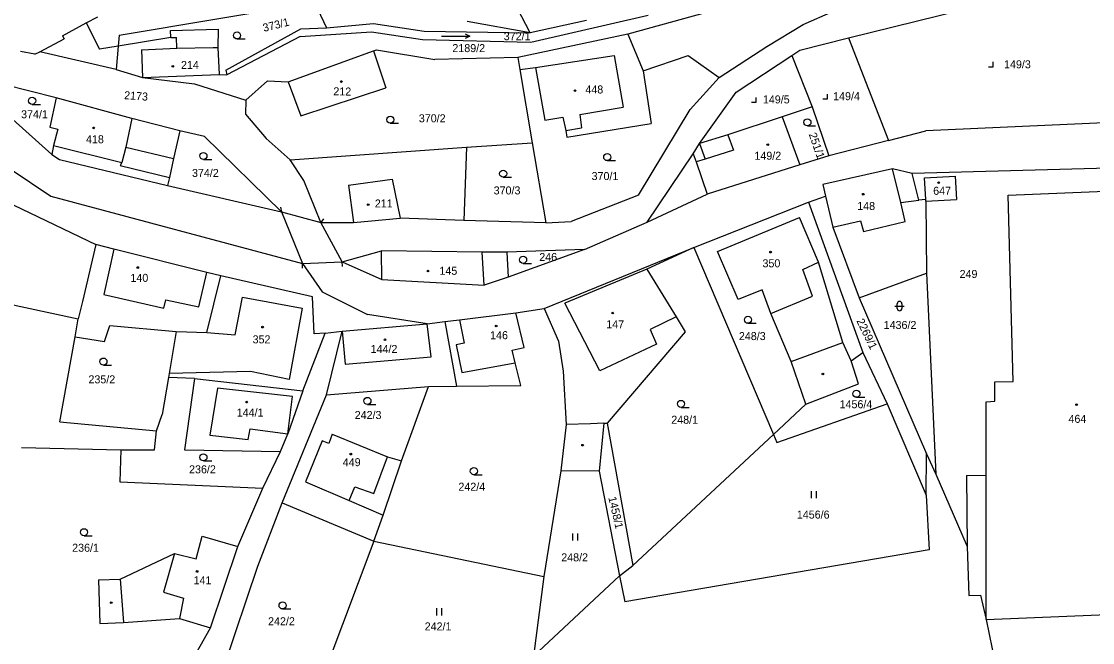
# Model space of a CAD drawing. Extents: x -717507 to -715515, y -957700 to -954941.
# Drawn here: x -717201.2 to -716973.6, y -957575.6 to -957443.7 of the extents above; entities that cross this region are included whole.
import ezdxf

# ---------------------------------------------------------------- set-up
doc = ezdxf.new("R2010")
doc.units = 0
for name, color, linetype in [('Hranice parcel', 7, 'Continuous'), ('Parcelní čísla', 7, 'Continuous'), ('Vnitřní kresba', 7, 'Continuous'), ('Značky budov', 7, 'Continuous'), ('Značky kultur', 7, 'Continuous')]:
    doc.layers.add(name, color=color, linetype=linetype)

msp = doc.modelspace()

# ---------------------------------------------------------------- linework, layer by layer
at = {"layer": 'Hranice parcel'}
for points in [[(-717028.63, -957434.3), (-717072.34, -957446.43)], [(-717025.46, -957447.15), (-716968.22, -957433.04)], [(-717093.05, -957446.09), (-717097.51, -957437.46)], [(-717180.41, -957446.62), (-717138.91, -957439.67)], [(-717138.91, -957439.67), (-717136.37, -957445.05)], [(-717035.09, -957444.35), (-717028.62, -957441.53)], [(-717187.43, -957444), (-717184.92, -957442.75)], [(-717187.43, -957444), (-717184.56, -957449.6)], [(-717093.05, -957446.09), (-717106.48, -957443.69)], [(-717081.13, -957443.5), (-717093.05, -957446.09)], [(-717092.95, -957448.11), (-717068.02, -957442.34)], [(-717169.47, -957445.61), (-717159.36, -957445.32)], [(-717169.45, -957447.09), (-717169.47, -957445.61)], [(-717159.36, -957445.32), (-717159.42, -957449.22)], [(-717157.74, -957454.03), (-717141.81, -957445.24)], [(-717141.93, -957446.89), (-717126.79, -957445.88)], [(-717141.81, -957445.24), (-717136.37, -957445.05)], [(-717136.37, -957445.05), (-717126.34, -957444.17)], [(-717126.79, -957445.88), (-717115.93, -957447.56)], [(-717126.34, -957444.17), (-717115.59, -957445.78)], [(-717115.59, -957445.78), (-717093.05, -957446.09)], [(-717042.77, -957449.01), (-717035.09, -957444.35)], [(-717180.41, -957446.62), (-717180.59, -957448.94)], [(-717169.45, -957447.09), (-717180.59, -957448.94)], [(-717141.93, -957446.89), (-717157.56, -957455.07)], [(-717115.93, -957447.56), (-717092.95, -957448.11)], [(-717072.34, -957446.43), (-717095.67, -957451.33)], [(-717072.34, -957446.43), (-717069.05, -957454.18)], [(-717035.77, -957449.77), (-717025.46, -957447.15)], [(-717025.46, -957447.15), (-717016.95, -957469)], [(-717198.31, -957450.67), (-717201.36, -957450.06)], [(-717198.31, -957450.67), (-717197.27, -957450.18)], [(-717181.03, -957453.94), (-717197.27, -957450.18)], [(-717180.59, -957448.94), (-717184.56, -957449.6)], [(-717180.59, -957448.94), (-717181.03, -957453.94)], [(-717159.42, -957449.22), (-717159.19, -957454.99)], [(-717144.46, -957456.53), (-717126.36, -957449.93)], [(-717126.36, -957449.93), (-717125.74, -957449.76)], [(-717126.36, -957449.93), (-717123.74, -957457.8)], [(-717125.74, -957449.76), (-717113.32, -957451.77)], [(-717069.05, -957454.18), (-717059.51, -957450.93)], [(-717059.51, -957450.93), (-717052.92, -957455.57)], [(-717052.92, -957455.57), (-717042.77, -957449.01)], [(-717049.33, -957458.69), (-717037.48, -957450.93)], [(-717037.48, -957450.93), (-717035.77, -957449.77)], [(-717037.48, -957450.93), (-717033.16, -957461.87)], [(-717095.67, -957451.33), (-717113.32, -957451.77)], [(-717095.67, -957451.33), (-717095.24, -957453.89)], [(-717181.03, -957453.94), (-717175.43, -957455.61)], [(-717175.43, -957455.61), (-717159.19, -957454.99)], [(-717159.19, -957454.99), (-717157.56, -957455.07)], [(-717157.74, -957454.03), (-717157.56, -957455.07)], [(-717095.24, -957453.89), (-717091.93, -957453.51)], [(-717095.24, -957453.89), (-717092.62, -957469.46)], [(-717091.93, -957453.51), (-717089.99, -957464.66)], [(-717069.05, -957454.18), (-717067.37, -957465.41)], [(-717193.77, -957459.92), (-717205, -957457.07)], [(-717175.43, -957455.61), (-717164.4, -957456.96)], [(-717164.4, -957456.96), (-717153.47, -957460.44)], [(-717153.47, -957460.44), (-717148.92, -957456.32)], [(-717148.92, -957456.32), (-717144.46, -957456.53)], [(-717144.46, -957456.53), (-717141.78, -957463.74)], [(-717059.09, -957462.41), (-717052.92, -957455.57)], [(-717193.77, -957459.92), (-717195.11, -957466.17)], [(-717177.68, -957464.34), (-717193.77, -957459.92)], [(-717141.78, -957463.74), (-717123.74, -957457.8)], [(-717057.06, -957469.61), (-717049.33, -957458.69)], [(-717205.86, -957462.08), (-717194.69, -957471.98)], [(-717153.47, -957460.44), (-717153.59, -957463.38)], [(-717033.16, -957461.87), (-717039.53, -957463.97)], [(-717033.16, -957461.87), (-717029.62, -957472.21)], [(-717167.54, -957466.91), (-717177.68, -957464.34)], [(-717153.59, -957463.38), (-717149.18, -957468.59)], [(-717089.99, -957464.66), (-717086.13, -957464.01)], [(-717086.13, -957464.01), (-717085.52, -957466.88)], [(-717070.07, -957480.59), (-717059.09, -957462.41)], [(-717039.53, -957463.97), (-717051.06, -957467.75)], [(-717039.53, -957463.97), (-717035.77, -957474.16)], [(-717195.11, -957466.17), (-717193.4, -957466.6)], [(-717193.4, -957466.6), (-717194.35, -957470.02)], [(-717085.52, -957466.88), (-717085.28, -957468.31)], [(-717085.28, -957468.31), (-717067.37, -957465.41)], [(-716963.15, -957464.91), (-717009.03, -957466.92)], [(-717167.54, -957466.91), (-717168.88, -957472.83)], [(-717162.3, -957468.13), (-717167.54, -957466.91)], [(-717162.3, -957468.13), (-717145.88, -957484.13)], [(-717144.06, -957473.12), (-717149.18, -957468.59)], [(-717051.06, -957467.75), (-717057.06, -957469.61)], [(-717016.95, -957469), (-717029.62, -957472.21)], [(-717016.95, -957469), (-717009.03, -957466.92)], [(-717194.35, -957470.02), (-717194.69, -957471.98)], [(-717144.06, -957473.12), (-717106.59, -957470.37)], [(-717106.59, -957470.37), (-717107.17, -957485.98)], [(-717106.59, -957470.37), (-717092.62, -957469.46)], [(-717092.62, -957469.46), (-717089.76, -957486.46)], [(-717058.43, -957471.81), (-717057.06, -957469.61)], [(-717194.69, -957471.98), (-717193.1, -957473.01)], [(-717193.1, -957473.01), (-717170.1, -957478.51)], [(-717168.88, -957472.83), (-717169.68, -957476.86)], [(-717141.13, -957477.45), (-717144.06, -957473.12)], [(-717068.19, -957486.31), (-717058.43, -957471.81)], [(-717029.62, -957472.21), (-717035.77, -957474.16)], [(-717203.32, -957475.14), (-717194.9, -957480.82)], [(-717035.77, -957474.16), (-717055.46, -957480.42)], [(-717016.05, -957474.97), (-717030.89, -957478.35)], [(-717014.34, -957482.17), (-717016.05, -957474.97)], [(-717011.93, -957476.02), (-717016.05, -957474.97)], [(-716967.49, -957474.81), (-717011.93, -957476.02)], [(-717213.48, -957477.61), (-717185.38, -957491.11)], [(-717169.68, -957476.86), (-717170.1, -957478.51)], [(-717137.54, -957486.43), (-717141.13, -957477.45)], [(-717009.28, -957476.92), (-717002.77, -957476.53)], [(-717009, -957481.49), (-717009.28, -957476.92)], [(-717002.77, -957476.53), (-717002.47, -957481.5)], [(-717170.1, -957478.51), (-717145.88, -957484.13)], [(-717068.19, -957486.31), (-717055.46, -957480.42)], [(-717030.89, -957478.35), (-717030.32, -957480.81)], [(-716991.53, -957480.6), (-716967.46, -957479.6)], [(-717194.9, -957480.82), (-717141.44, -957495.09)], [(-717070.07, -957480.59), (-717084.38, -957486.18)], [(-717058.33, -957491.7), (-717033.93, -957482.12)], [(-717033.93, -957482.12), (-717030.32, -957480.81)], [(-717033.93, -957482.12), (-717022.39, -957514.05)], [(-717030.32, -957480.81), (-717028.79, -957487.41)], [(-717014.34, -957482.17), (-717010.48, -957481.69)], [(-717009.8, -957481.6), (-717010.48, -957481.69)], [(-717009, -957481.49), (-717009.8, -957481.6)], [(-717008.98, -957481.89), (-717009, -957481.49)], [(-717008.98, -957481.89), (-717002.47, -957481.5)], [(-717008.98, -957481.89), (-717008.84, -957497.16)], [(-716990.41, -957520.17), (-716991.53, -957480.6)], [(-717145.88, -957484.13), (-717137.54, -957486.43)], [(-717137.54, -957486.43), (-717130.63, -957486.43)], [(-717130.63, -957486.43), (-717120.68, -957485.5)], [(-717107.17, -957485.98), (-717120.68, -957485.5)], [(-717089.76, -957486.46), (-717107.17, -957485.98)], [(-717089.76, -957486.46), (-717084.38, -957486.18)], [(-717081.51, -957492.16), (-717068.19, -957486.31)], [(-717053.24, -957492.55), (-717035.85, -957485.32)], [(-717031.82, -957494.84), (-717035.85, -957485.32)], [(-717028.79, -957487.41), (-717023.18, -957502.44)], [(-717185.38, -957491.11), (-717188.19, -957503.16)], [(-717181.51, -957492.06), (-717185.38, -957491.11)], [(-717090.11, -957504.67), (-717058.33, -957491.7)], [(-717058.33, -957491.7), (-717068.25, -957496.31)], [(-717058.33, -957491.7), (-717041.39, -957531.43)], [(-717161.76, -957497), (-717181.51, -957492.06)], [(-717133.05, -957494.79), (-717124.65, -957492.41)], [(-717103.24, -957492.71), (-717124.65, -957492.41)], [(-717098.05, -957492.71), (-717103.24, -957492.71)], [(-717081.51, -957492.16), (-717098.05, -957492.71)], [(-717098.05, -957492.71), (-717097.75, -957498.02)], [(-717081.51, -957492.16), (-717097.75, -957498.02)], [(-717048.89, -957502.76), (-717053.24, -957492.55)], [(-717141.44, -957495.09), (-717133.05, -957494.79)], [(-717141.44, -957495.09), (-717137.27, -957501.12)], [(-717133.05, -957494.79), (-717124.59, -957498.51)], [(-717068.25, -957496.31), (-717062.08, -957506.44)], [(-717026.61, -957511.91), (-717031.82, -957494.84)], [(-717158.82, -957497.71), (-717161.76, -957497)], [(-717161.75, -957509.8), (-717158.82, -957497.71)], [(-717139.31, -957502.22), (-717158.82, -957497.71)], [(-717124.59, -957498.51), (-717102.87, -957499.73)], [(-717097.75, -957498.02), (-717102.87, -957499.73)], [(-717023.18, -957502.44), (-717008.84, -957497.16)], [(-717008.84, -957497.16), (-717006.9, -957539.85)], [(-717043.76, -957500.74), (-717048.89, -957502.76)], [(-717041.93, -957505.75), (-717043.76, -957500.74)], [(-717210.55, -957502.23), (-717189.11, -957506.88)], [(-717188.19, -957503.16), (-717189.11, -957506.88)], [(-717138.99, -957510.04), (-717139.31, -957502.22)], [(-717137.27, -957501.12), (-717127.67, -957505.92)], [(-717023.18, -957502.44), (-717008.86, -957535.57)], [(-717096.14, -957505.61), (-717090.11, -957504.67)], [(-717090.11, -957504.67), (-717087.03, -957511.63)], [(-717189.78, -957510.69), (-717189.11, -957506.88)], [(-717114.94, -957507.92), (-717127.67, -957505.92)], [(-717114.94, -957507.92), (-717111.18, -957507.46)], [(-717111.18, -957507.46), (-717108.1, -957507.09)], [(-717111.18, -957507.46), (-717108.7, -957521.15)], [(-717108.1, -957507.09), (-717096.14, -957505.61)], [(-717094.38, -957512.94), (-717096.14, -957505.61)], [(-717062.08, -957506.44), (-717060.13, -957509.62)], [(-717037.59, -957515.94), (-717041.93, -957505.75)], [(-717183.52, -957511.7), (-717182.39, -957508.31)], [(-717182.39, -957508.31), (-717168.26, -957509.57)], [(-717168.26, -957509.57), (-717169.79, -957518.49)], [(-717168.26, -957509.57), (-717161.75, -957509.8)], [(-717141.4, -957522.13), (-717136.64, -957509.89)], [(-717136.64, -957509.89), (-717138.99, -957510.04)], [(-717136.64, -957509.89), (-717133, -957509.5)], [(-717136.37, -957523.04), (-717133, -957509.5)], [(-717133, -957509.5), (-717114.94, -957507.92)], [(-717060.13, -957509.62), (-717076.7, -957529.01)], [(-717193.01, -957528.76), (-717189.78, -957510.69)], [(-717189.78, -957510.69), (-717183.52, -957511.7)], [(-717087.03, -957511.63), (-717086.05, -957517.95)], [(-717024.9, -957515.82), (-717026.61, -957511.91)], [(-717096.89, -957513.52), (-717094.38, -957512.94)], [(-717096.28, -957516.18), (-717096.89, -957513.52)], [(-717024.9, -957515.82), (-717022.39, -957514.05)], [(-717022.39, -957514.05), (-717017.2, -957524.92)], [(-717095.06, -957521.06), (-717096.28, -957516.18)], [(-717034.48, -957524.98), (-717037.59, -957515.94)], [(-717023.31, -957520.64), (-717024.9, -957515.82)], [(-717169.79, -957518.49), (-717169.93, -957519.31)], [(-717086.05, -957517.95), (-717085.4, -957529.33)], [(-717169.93, -957519.31), (-717171.28, -957527.2)], [(-717164.39, -957519.57), (-717169.93, -957519.31)], [(-717164.39, -957519.57), (-717166.52, -957534.71)], [(-717164.39, -957519.57), (-717141.4, -957522.13)], [(-717136.37, -957523.04), (-717114.64, -957521.27)], [(-717120.38, -957537.03), (-717114.64, -957521.27)], [(-717114.64, -957521.27), (-717108.7, -957521.15)], [(-717108.7, -957521.15), (-717095.06, -957521.06)], [(-717034.48, -957524.98), (-717023.31, -957520.64)], [(-716994.33, -957524.39), (-716994.31, -957520.27)], [(-716994.31, -957520.27), (-716990.41, -957520.17)], [(-717145.76, -957545.97), (-717136.37, -957523.04)], [(-717141.4, -957522.13), (-717144.55, -957531.32)], [(-717041.39, -957531.43), (-717034.48, -957524.98)], [(-717040.65, -957533.12), (-717017.2, -957524.92)], [(-717017.2, -957524.92), (-717008.92, -957544.31)], [(-716996.2, -957524.51), (-716994.33, -957524.39)], [(-716996.2, -957540.06), (-716996.2, -957524.51)], [(-717172.44, -957530.66), (-717171.28, -957527.2)], [(-717193.01, -957528.76), (-717172.44, -957530.66)], [(-717085.4, -957529.33), (-717086.56, -957539.15)], [(-717077.43, -957529.01), (-717078.38, -957539.22)], [(-717077.43, -957529.01), (-717076.7, -957529.01)], [(-717076.7, -957529.01), (-717071.23, -957559.25)], [(-717172.87, -957534.66), (-717172.44, -957530.66)], [(-717146.13, -957535.03), (-717144.55, -957531.32)], [(-717137.29, -957532.75), (-717140.83, -957541.48)], [(-717135.82, -957533.36), (-717137.29, -957532.75)], [(-717135.15, -957531.35), (-717135.82, -957533.36)], [(-717135.15, -957531.35), (-717123.37, -957536.17)], [(-717071.23, -957559.25), (-717041.39, -957531.43)], [(-717041.39, -957531.43), (-717040.65, -957533.12)], [(-717201.19, -957534.18), (-717180.07, -957534.67)], [(-717180.07, -957534.67), (-717180.26, -957541.49)], [(-717180.07, -957534.67), (-717172.87, -957534.66)], [(-717166.52, -957534.71), (-717146.13, -957535.03)], [(-717149.91, -957542.85), (-717146.13, -957535.03)], [(-717124.28, -957548.57), (-717120.38, -957537.03)], [(-717123.37, -957536.17), (-717120.38, -957537.03)], [(-717008.92, -957544.31), (-717008.86, -957535.57)], [(-717008.86, -957535.57), (-717006.9, -957539.85)], [(-717086.56, -957539.15), (-717090.19, -957561.6)], [(-717078.38, -957539.22), (-717086.56, -957539.15)], [(-717078.38, -957539.22), (-717074.1, -957561.45)], [(-717180.26, -957541.49), (-717149.91, -957542.85)], [(-717140.83, -957541.48), (-717131.55, -957545.45)], [(-717006.9, -957539.85), (-717000.23, -957555.2)], [(-717000.35, -957540.18), (-716996.2, -957540.06)], [(-717000.35, -957540.18), (-717000.23, -957555.2)], [(-717155.2, -957555.23), (-717149.91, -957542.85)], [(-717150.95, -957559.4), (-717145.76, -957545.97)], [(-717145.76, -957545.97), (-717126.31, -957554.08)], [(-717131.55, -957545.45), (-717124.28, -957548.57)], [(-717008.92, -957544.31), (-717008.31, -957555.9)], [(-717126.31, -957554.08), (-717124.28, -957548.57)], [(-717164.05, -957557.87), (-717162.74, -957553.04)], [(-717162.74, -957553.04), (-717155.2, -957555.23)], [(-717160.99, -957572.5), (-717155.2, -957555.23)], [(-717126.31, -957554.08), (-717136.29, -957580.64)], [(-717126.31, -957554.08), (-717090.19, -957561.6)], [(-717000.23, -957555.2), (-716999.87, -957565.64)], [(-717180.21, -957562.19), (-717168.68, -957556.69)], [(-717168.68, -957556.69), (-717164.05, -957557.87)], [(-717008.31, -957555.9), (-717072.94, -957567.01)], [(-717158.11, -957580.62), (-717150.95, -957559.4)], [(-717074.1, -957561.45), (-717071.23, -957559.25)], [(-717184.79, -957562.31), (-717180.21, -957562.19)], [(-717184.79, -957562.31), (-717184.49, -957571.59)], [(-717092.37, -957578.51), (-717074.1, -957561.45)], [(-717090.19, -957561.6), (-717092.37, -957578.51)], [(-717074.1, -957561.45), (-717072.94, -957567.01)], [(-716999.87, -957565.64), (-716997.36, -957565.58)], [(-716997.36, -957565.58), (-716996.16, -957570.71)], [(-717184.49, -957571.59), (-717179.48, -957571.34)], [(-717179.48, -957571.34), (-717167.58, -957570.55)], [(-717167.58, -957570.55), (-717160.99, -957572.5)], [(-716996.16, -957570.71), (-716963.62, -957569.41)], [(-716996.16, -957570.71), (-716988.5, -957608.12)], [(-717165.38, -957580.26), (-717160.99, -957572.5)]]:
    msp.add_lwpolyline(points, dxfattribs=at)
at = {"layer": 'Vnitřní kresba'}
for points in [[(-717192.45, -957446.76), (-717187.43, -957444)], [(-717197.27, -957450.18), (-717192.08, -957447.37)], [(-717192.45, -957446.76), (-717192.08, -957447.37)], [(-717169.45, -957447.09), (-717168.23, -957447.11)], [(-717168.17, -957449.38), (-717168.23, -957447.11)], [(-717175.66, -957449.7), (-717168.17, -957449.38)], [(-717175.66, -957449.7), (-717175.43, -957455.61)], [(-717168.17, -957449.38), (-717160.41, -957449.23)], [(-717160.41, -957449.23), (-717159.42, -957449.22)], [(-717091.93, -957453.51), (-717075.24, -957450.94)], [(-717075.24, -957450.94), (-717073.29, -957461.9)], [(-717082.53, -957463.43), (-717073.29, -957461.9)], [(-717177.68, -957464.34), (-717179.02, -957470.39)], [(-717082.53, -957463.43), (-717082.13, -957466.33)], [(-717085.52, -957466.88), (-717082.13, -957466.33)], [(-717051.06, -957467.75), (-717049.9, -957471.05)], [(-717194.35, -957470.02), (-717179.87, -957473.63)], [(-717179.02, -957470.39), (-717179.87, -957473.63)], [(-717179.02, -957470.39), (-717168.88, -957472.83)], [(-717057.06, -957469.61), (-717055.91, -957472.97)], [(-717049.9, -957471.05), (-717055.91, -957472.97)], [(-717179.87, -957473.63), (-717180.18, -957474.3)], [(-717058.43, -957471.81), (-717057.8, -957473.55)], [(-717055.91, -957472.97), (-717057.8, -957473.55)], [(-717057.8, -957473.55), (-717055.46, -957480.42)], [(-717180.18, -957474.3), (-717169.68, -957476.86)], [(-717131.67, -957478.49), (-717122.4, -957477.21)], [(-717122.4, -957477.21), (-717120.68, -957485.5)], [(-717010.48, -957481.69), (-717011.93, -957476.02)], [(-717131.67, -957478.49), (-717130.63, -957486.43)], [(-717013.39, -957486.16), (-717014.34, -957482.17)], [(-717145.88, -957484.13), (-717141.44, -957495.09)], [(-717133.05, -957494.79), (-717137.54, -957486.43)], [(-717028.79, -957487.41), (-717022.88, -957486.02)], [(-717022.88, -957486.02), (-717022.26, -957488.29)], [(-717022.26, -957488.29), (-717013.39, -957486.16)], [(-717181.51, -957492.06), (-717183.67, -957501.71)], [(-717124.59, -957498.51), (-717124.65, -957492.41)], [(-717102.87, -957499.73), (-717103.24, -957492.71)], [(-717068.25, -957496.31), (-717085.68, -957503.51)], [(-717035.13, -957496.38), (-717031.82, -957494.84)], [(-717033.08, -957502.08), (-717035.13, -957496.38)], [(-717163.47, -957504.33), (-717161.76, -957497)], [(-717183.67, -957501.71), (-717170.89, -957504.61)], [(-717170.89, -957504.61), (-717170.52, -957502.81)], [(-717170.52, -957502.81), (-717163.47, -957504.33)], [(-717155.74, -957510.3), (-717154.17, -957502.24)], [(-717154.17, -957502.24), (-717141.49, -957504.58)], [(-717041.93, -957505.75), (-717033.08, -957502.08)], [(-717141.49, -957504.58), (-717144.27, -957519.77)], [(-717078.29, -957517.9), (-717085.68, -957503.51)], [(-717108.1, -957507.09), (-717107.08, -957512.05)], [(-717062.08, -957506.44), (-717067.54, -957509.1)], [(-717161.75, -957509.8), (-717155.74, -957510.3)], [(-717133, -957509.5), (-717132.39, -957516.47)], [(-717114.11, -957514.92), (-717114.94, -957507.92)], [(-717067.54, -957509.1), (-717066.26, -957512.22)], [(-717107.08, -957512.05), (-717108.79, -957512.39)], [(-717108.79, -957512.39), (-717107.6, -957518.25)], [(-717066.26, -957512.22), (-717078.29, -957517.9)], [(-717037.59, -957515.94), (-717026.61, -957511.91)], [(-717132.39, -957516.47), (-717114.11, -957514.92)], [(-717107.6, -957518.25), (-717096.28, -957516.18)], [(-717152.51, -957518.04), (-717169.79, -957518.49)], [(-717144.27, -957519.77), (-717152.51, -957518.04)], [(-717159.53, -957521.56), (-717161.15, -957531.57)], [(-717143.58, -957523.34), (-717159.53, -957521.56)], [(-717144.55, -957531.32), (-717143.58, -957523.34)], [(-717152.97, -957532.52), (-717152.58, -957530.2)], [(-717152.58, -957530.2), (-717144.55, -957531.32)], [(-717080.28, -957529.14), (-717085.4, -957529.33)], [(-717077.43, -957529.01), (-717080.28, -957529.14)], [(-717161.15, -957531.57), (-717152.97, -957532.52)], [(-717126.3, -957543.99), (-717123.37, -957536.17)], [(-716996.16, -957570.71), (-716996.2, -957540.06)], [(-717131.55, -957545.45), (-717130.33, -957542.58)], [(-717130.33, -957542.58), (-717126.3, -957543.99)], [(-717168.68, -957556.69), (-717171, -957564.93)], [(-717180.21, -957562.19), (-717179.48, -957571.34)], [(-717171, -957564.93), (-717166.73, -957566.22)], [(-717166.73, -957566.22), (-717167.58, -957570.55)]]:
    msp.add_lwpolyline(points, dxfattribs=at)
at = {"layer": 'Značky budov'}
for centre in [(-717169, -957453.22), (-717133.18, -957456.46), (-717083.56, -957458.39), (-717185.81, -957466.31), (-717042.58, -957469.87), (-717006.27, -957477.94), (-717022.3, -957480.39), (-717127.49, -957482.61), (-717041.99, -957492.69), (-717176.45, -957495.97), (-717114.77, -957496.71), (-717075.54, -957505.63), (-717149.94, -957508.62), (-717100.28, -957508.39), (-717123.93, -957511.32), (-717153.31, -957524.56), (-716976.97, -957525.09), (-717081.94, -957533.7), (-717131.19, -957535.61), (-717163.84, -957560.53)]:
    msp.add_circle(centre, 0.175, dxfattribs=at)
at = {"layer": 'Značky kultur'}
for points in [[(-717106.91, -957446.31), (-717105.91, -957446.81), (-717106.91, -957447.31)], [(-717155.35, -957447.42), (-717153.6, -957447.42)], [(-717111.91, -957446.81), (-717105.91, -957446.81)], [(-716995.66, -957453.31), (-716994.66, -957453.31), (-716994.66, -957452.31)], [(-717046.06, -957460.84), (-717045.06, -957460.84), (-717045.06, -957459.84)], [(-717030.88, -957460.13), (-717029.88, -957460.13), (-717029.88, -957459.13)], [(-717198.89, -957461.31), (-717197.14, -957461.31)], [(-717122.79, -957465.32), (-717121.04, -957465.32)], [(-717034.16, -957465.87), (-717032.41, -957465.87)], [(-717162.49, -957473.02), (-717160.74, -957473.02)], [(-717076.7, -957473.26), (-717074.95, -957473.26)], [(-717098.81, -957476.79), (-717097.06, -957476.79)], [(-717146.1, -957483.17), (-717145.88, -957484.13)], [(-717136.99, -957485.6), (-717137.54, -957486.43)], [(-717141.45, -957496.08), (-717141.44, -957495.09)], [(-717132.98, -957495.78), (-717133.05, -957494.79)], [(-717094.57, -957495.08), (-717092.82, -957495.08)], [(-717015.57, -957504.15), (-717013.57, -957504.15)], [(-717015.07, -957504.65), (-717015.07, -957503.65)], [(-717014.07, -957503.65), (-717014.07, -957504.65)], [(-717046.8, -957507.82), (-717045.05, -957507.82)], [(-717183.75, -957516.69), (-717182, -957516.69)], [(-717023.74, -957523.53), (-717021.99, -957523.53)], [(-717127.65, -957525.05), (-717125.9, -957525.05)], [(-717061.02, -957525.68), (-717059.27, -957525.68)], [(-717162.49, -957537.03), (-717160.74, -957537.03)], [(-717105.04, -957539.97), (-717103.29, -957539.97)], [(-717033.26, -957544.97), (-717033.26, -957543.47)], [(-717032.22, -957544.97), (-717032.22, -957543.47)], [(-717187.87, -957552.94), (-717186.12, -957552.94)], [(-717083.98, -957553.96), (-717083.98, -957552.46)], [(-717082.94, -957553.96), (-717082.94, -957552.46)], [(-717145.69, -957568.5), (-717143.94, -957568.5)], [(-717112.9, -957569.85), (-717112.9, -957568.35)], [(-717111.86, -957569.85), (-717111.86, -957568.35)]]:
    msp.add_lwpolyline(points, dxfattribs=at)
for centre, radius in [((-717155.35, -957446.67), 0.75), ((-717198.89, -957460.56), 0.75), ((-717122.79, -957464.57), 0.75), ((-717034.16, -957465.12), 0.75), ((-717162.49, -957472.27), 0.75), ((-717076.7, -957472.51), 0.75), ((-717098.81, -957476.04), 0.75), ((-717094.57, -957494.33), 0.75), ((-717046.8, -957507.07), 0.75), ((-717183.75, -957515.94), 0.75), ((-717030.88, -957518.57), 0.175), ((-717127.65, -957524.3), 0.75), ((-717023.74, -957522.78), 0.75), ((-717061.02, -957524.93), 0.75), ((-717162.49, -957536.28), 0.75), ((-717105.04, -957539.22), 0.75), ((-717187.87, -957552.19), 0.75), ((-717182.09, -957567.17), 0.175), ((-717145.69, -957567.75), 0.75)]:
    msp.add_circle(centre, radius, dxfattribs=at)
for centre, start, end in [((-717014.57, -957503.65), 0.101, 180.0014), ((-717014.57, -957504.65), 180.1024, 0.0029)]:
    msp.add_arc(centre, 0.5, start, end, dxfattribs=at)

# ---------------------------------------------------------------- texts
at = {"layer": 'Parcelní čísla'}
for s, rotation, p in [('373/1', 14.1001, (-717149.65, -957445.93)), ('212', 359.0029, (-717134.91, -957459.38)), ('2173', 356.1028, (-717179.39, -957460.19)), ('251/1', 289.3023, (-717033.91, -957467.66)), ('2269/1', 295.9024, (-717023.8, -957507.29)), ('1458/1', 283.2023, (-717076.48, -957544.83))]:
    msp.add_text(s, height=1.7, rotation=rotation, dxfattribs=at).set_placement(p)
for s, p in [('372/1', (-717098.69, -957447.69)), ('2189/2', (-717109.6, -957450.21)), ('214', (-717167.27, -957453.79)), ('149/3', (-716992.38, -957453.65)), ('448', (-717081.34, -957459)), ('149/5', (-717043.62, -957461.11)), ('149/4', (-717028.7, -957460.42)), ('374/1', (-717201.24, -957464.27)), ('370/2', (-717116.73, -957465.12)), ('418', (-717187.45, -957469.57)), ('149/2', (-717045.42, -957473.07)), ('374/2', (-717164.93, -957476.73)), ('370/1', (-717080.02, -957477.39)), ('370/3', (-717100.83, -957480.44)), ('647', (-717007.44, -957480.52)), ('211', (-717126.08, -957483.21)), ('148', (-717023.58, -957483.75)), ('246', (-717091.14, -957494.59)), ('350', (-717043.71, -957495.92)), ('145', (-717112.35, -957497.51)), ('249', (-717001.83, -957498.19)), ('140', (-717178.01, -957499.01)), ('147', (-717076.9, -957508.88)), ('1436/2', (-717017.96, -957509.02)), ('146', (-717101.58, -957511.19)), ('248/3', (-717048.72, -957511.38)), ('352', (-717152.05, -957512.08)), ('144/2', (-717126.97, -957514.12)), ('235/2', (-717186.93, -957520.57)), ('144/1', (-717155.42, -957527.62)), ('1456/4', (-717027.33, -957525.86)), ('242/3', (-717130.36, -957528.15)), ('248/1', (-717063.09, -957529.15)), ('464', (-716978.69, -957528.96)), ('449', (-717132.89, -957538.17)), ('236/2', (-717165.55, -957539.68)), ('242/4', (-717108.32, -957543.38)), ('1456/6', (-717036.41, -957549.3)), ('236/1', (-717190.39, -957556.34)), ('248/2', (-717086.47, -957558.38)), ('141', (-717164.6, -957563.25)), ('242/2', (-717148.76, -957571.95)), ('242/1', (-717115.49, -957573.05))]:
    msp.add_text(s, height=1.7, dxfattribs=at).set_placement(p)

doc.saveas('drawing.dxf')
